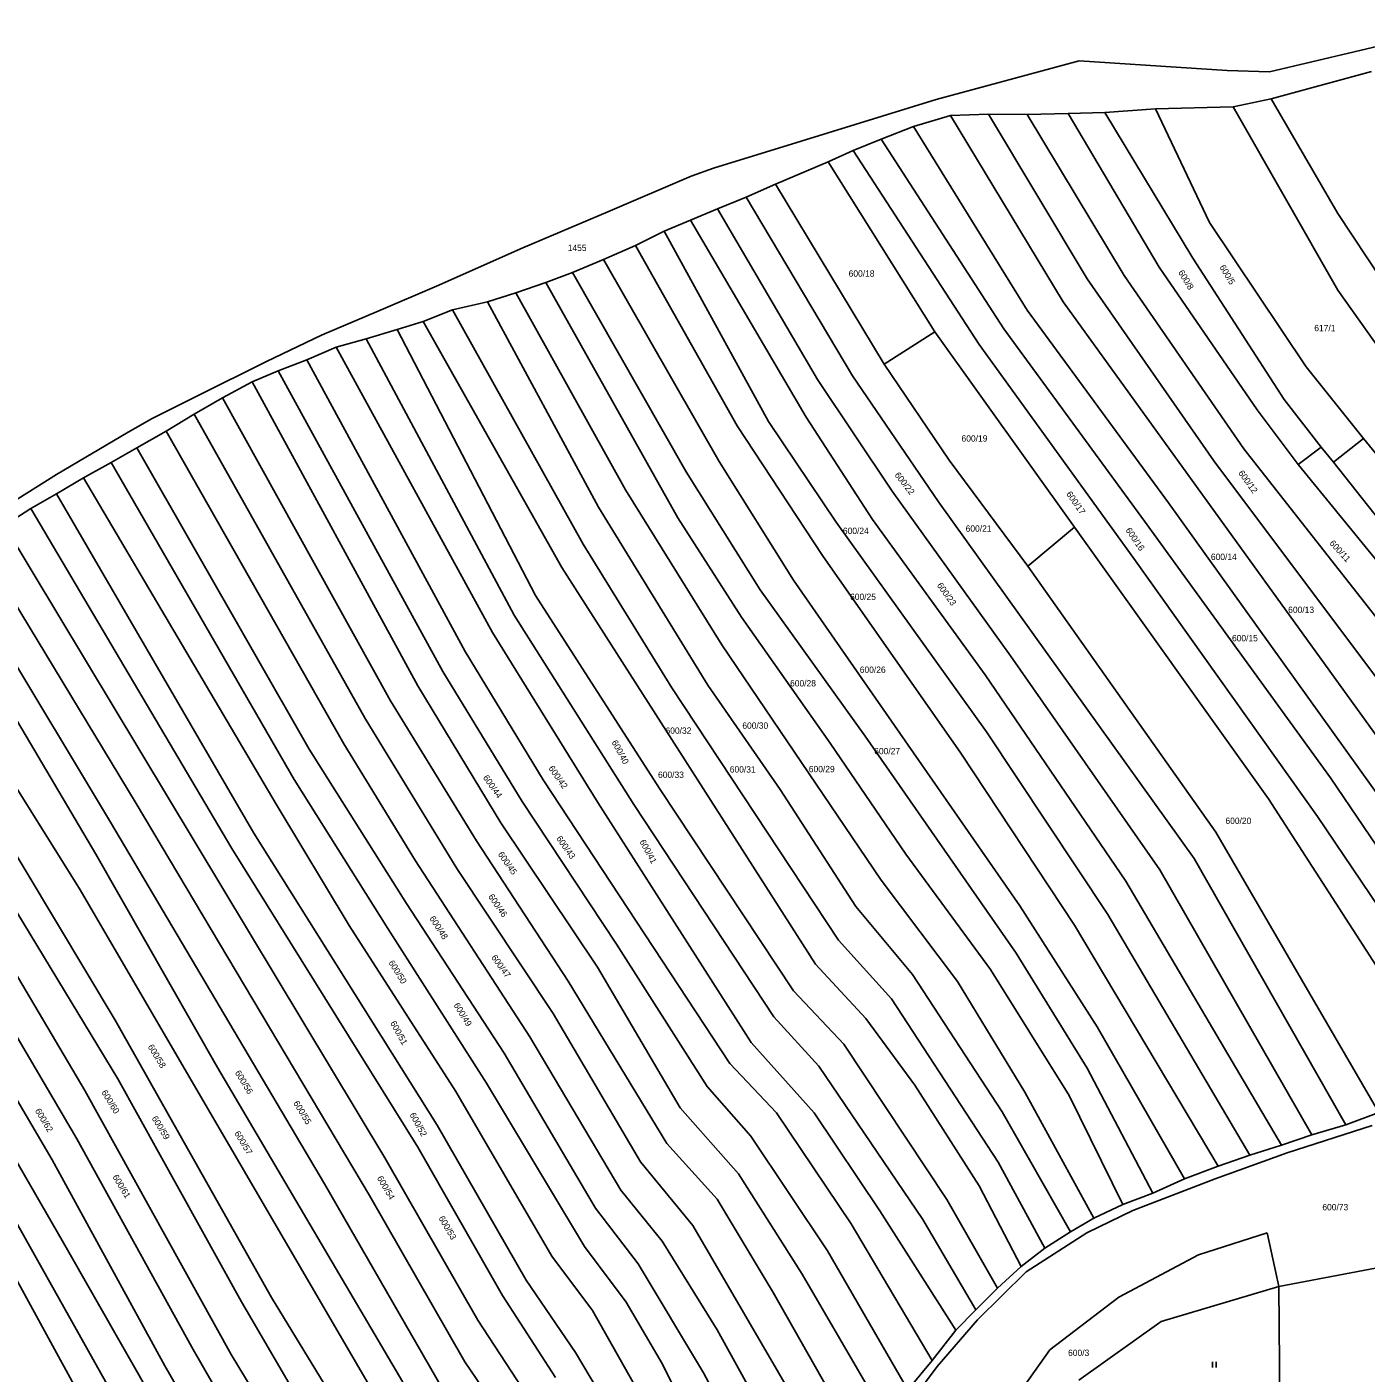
# Model space of a CAD drawing. Extents: x -580630 to -576196, y -1189024 to -1183567.
# Drawn here: x -578490.7 to -578130.8, y -1184779.6 to -1184417.7 of the extents above; entities that cross this region are included whole.
import ezdxf

# ---------------------------------------------------------------- set-up
doc = ezdxf.new("R2010")
doc.units = 0
for name, color, linetype in [('Vrstva 1', 7, 'Continuous'), ('Vrstva 13', 7, 'Continuous'), ('Vrstva 18', 7, 'Continuous'), ('Vrstva 25', 7, 'Continuous'), ('Vrstva 6', 7, 'Continuous')]:
    doc.layers.add(name, color=color, linetype=linetype)

msp = doc.modelspace()

# ---------------------------------------------------------------- linework, layer by layer
at = {"layer": 'Vrstva 1'}
for p, q in [((-578156.31, -1184437.09), (-578129.38, -1184429.69)), ((-578187.46, -1184439.77), (-578201.05, -1184440.75)), ((-578187.46, -1184439.77), (-578166.55, -1184439.17)), ((-578172.89, -1184470.31), (-578187.46, -1184439.77)), ((-578166.55, -1184439.17), (-578156.31, -1184437.09)), ((-578166.55, -1184439.17), (-578138.38, -1184488.49)), ((-578156.31, -1184437.09), (-578138.42, -1184467.91)), ((-578252.43, -1184444.53), (-578242.55, -1184441.49)), ((-578232.31, -1184441.2), (-578242.55, -1184441.49)), ((-578221.93, -1184441.29), (-578232.31, -1184441.2)), ((-578210.85, -1184440.99), (-578221.93, -1184441.29)), ((-578201.05, -1184440.75), (-578210.85, -1184440.99)), ((-578261.15, -1184447.91), (-578252.43, -1184444.53)), ((-578268.68, -1184450.96), (-578275.4, -1184453.97)), ((-578261.15, -1184447.91), (-578268.68, -1184450.96)), ((-578275.4, -1184453.97), (-578289.57, -1184460.03)), ((-578297.45, -1184463.46), (-578289.57, -1184460.03)), ((-578305.17, -1184466.61), (-578297.45, -1184463.46)), ((-578305.17, -1184466.61), (-578312.43, -1184469.69)), ((-578138.42, -1184467.91), (-578094.43, -1184534.57)), ((-578319.47, -1184472.65), (-578327.2, -1184476.49)), ((-578312.43, -1184469.69), (-578319.47, -1184472.65)), ((-578146.91, -1184509.13), (-578172.89, -1184470.31)), ((-578327.2, -1184476.49), (-578335.73, -1184480.22)), ((-578344.12, -1184483.77), (-578335.73, -1184480.22)), ((-578344.12, -1184483.77), (-578351.26, -1184486.44)), ((-578359.37, -1184489.24), (-578351.26, -1184486.44)), ((-578366.97, -1184491.62), (-578359.37, -1184489.24)), ((-578138.38, -1184488.49), (-578086.6, -1184562)), ((-578376.38, -1184493.76), (-578384.2, -1184496.88)), ((-578376.38, -1184493.76), (-578366.97, -1184491.62)), ((-578384.2, -1184496.88), (-578391.26, -1184499.04)), ((-578407.59, -1184503.82), (-578399.53, -1184501.55)), ((-578391.26, -1184499.04), (-578399.53, -1184501.55)), ((-578415.53, -1184507.18), (-578407.59, -1184503.82)), ((-578423.24, -1184510.15), (-578415.53, -1184507.18)), ((-578131.54, -1184528.4), (-578146.91, -1184509.13)), ((-578423.24, -1184510.15), (-578430.23, -1184513.12)), ((-578430.23, -1184513.12), (-578438.2, -1184517.43)), ((-578438.2, -1184517.43), (-578445.8, -1184521.81)), ((-578453.35, -1184526.38), (-578445.8, -1184521.81)), ((-578453.35, -1184526.38), (-578461.15, -1184530.85)), ((-578461.15, -1184530.85), (-578468.08, -1184534.79)), ((-578131.54, -1184528.4), (-578119.43, -1184543.18)), ((-578475.52, -1184538.93), (-578468.08, -1184534.79)), ((-578482.77, -1184543.23), (-578475.52, -1184538.93)), ((-578482.77, -1184543.23), (-578489.64, -1184547.14)), ((-578496.8, -1184551.76), (-578489.64, -1184547.14)), ((-578127.39, -1184709.55), (-578136.23, -1184712.88)), ((-578153.56, -1184718.31), (-578145.43, -1184715.59)), ((-578129.17, -1184713.08), (-578152, -1184720.37)), ((-578136.23, -1184712.88), (-578145.43, -1184715.59)), ((-578162.11, -1184721.07), (-578153.56, -1184718.31)), ((-578152, -1184720.37), (-578171.4, -1184727.37)), ((-578170.61, -1184723.95), (-578162.11, -1184721.07)), ((-578179.6, -1184727.36), (-578170.61, -1184723.95)), ((-578171.4, -1184727.37), (-578193.55, -1184735.94)), ((-578179.6, -1184727.36), (-578188.1, -1184731.21)), ((-578196.23, -1184734.3), (-578188.1, -1184731.21)), ((-578193.55, -1184735.94), (-578205.86, -1184741.95)), ((-578196.23, -1184734.3), (-578203.97, -1184737.94)), ((-578203.97, -1184737.94), (-578210.31, -1184741.62)), ((-578205.86, -1184741.95), (-578222.2, -1184752.38)), ((-578210.31, -1184741.62), (-578217.16, -1184746.05)), ((-578223.52, -1184750.95), (-578217.16, -1184746.05)), ((-578108.43, -1184747.7), (-578154.28, -1184756.3)), ((-578229.92, -1184756.76), (-578223.52, -1184750.95)), ((-578222.2, -1184752.38), (-578235.29, -1184765.29)), ((-578235.69, -1184762.57), (-578229.92, -1184756.76)), ((-578154.28, -1184756.3), (-578185.88, -1184765.76)), ((-578235.69, -1184762.57), (-578241.12, -1184768.09)), ((-578235.29, -1184765.29), (-578246.12, -1184777.8)), ((-578185.88, -1184765.76), (-578208.03, -1184781.52)), ((-578241.12, -1184768.09), (-578247.45, -1184776.2)), ((-578247.45, -1184776.2), (-578253.94, -1184784.14)), ((-578246.12, -1184777.8), (-578270.55, -1184810.61))]:
    msp.add_line(p, q, dxfattribs=at)
at = {"layer": 'Vrstva 13'}
for p, q in [((-578156.78, -1184429.77), (-578105.77, -1184417.72)), ((-578207.91, -1184426.86), (-578246.37, -1184437.25)), ((-578168.12, -1184429.45), (-578207.91, -1184426.86)), ((-578156.78, -1184429.77), (-578168.12, -1184429.45)), ((-578246.37, -1184437.25), (-578282.66, -1184448.44)), ((-578282.66, -1184448.44), (-578306.17, -1184455.7)), ((-578312.25, -1184457.84), (-578334.61, -1184467.4)), ((-578306.17, -1184455.7), (-578312.25, -1184457.84)), ((-578334.61, -1184467.4), (-578357.46, -1184477.13)), ((-578357.46, -1184477.13), (-578380.66, -1184487.42)), ((-578380.66, -1184487.42), (-578396.11, -1184494.01)), ((-578396.11, -1184494.01), (-578411.56, -1184500.61)), ((-578411.56, -1184500.61), (-578426.36, -1184507.69)), ((-578426.36, -1184507.69), (-578444.93, -1184516.92)), ((-578444.93, -1184516.92), (-578457.09, -1184523.02)), ((-578457.09, -1184523.02), (-578463.5, -1184526.64)), ((-578463.5, -1184526.64), (-578482.74, -1184538.01)), ((-578482.74, -1184538.01), (-578495.55, -1184546.08))]:
    msp.add_line(p, q, dxfattribs=at)
at = {"layer": 'Vrstva 25'}
for p, q in [((-578172.08, -1184776.59), (-578172.08, -1184778.09)), ((-578171.08, -1184778.09), (-578171.08, -1184776.59))]:
    msp.add_line(p, q, dxfattribs=at)
at = {"layer": 'Vrstva 6'}
for p, q in [((-578242.55, -1184441.49), (-578212.23, -1184491.59)), ((-578232.31, -1184441.2), (-578205.82, -1184485.43)), ((-578221.93, -1184441.29), (-578195.84, -1184484.58)), ((-578210.85, -1184440.99), (-578186.47, -1184482.33)), ((-578201.05, -1184440.75), (-578177.42, -1184479.87)), ((-578221.92, -1184493.83), (-578252.43, -1184444.53)), ((-578268.68, -1184450.96), (-578234.81, -1184503.08)), ((-578228.22, -1184498.85), (-578261.15, -1184447.91)), ((-578275.4, -1184453.97), (-578246.75, -1184499.69)), ((-578289.57, -1184460.03), (-578260.33, -1184508.4)), ((-578268.89, -1184511.56), (-578297.45, -1184463.46)), ((-578278.3, -1184512.52), (-578305.17, -1184466.61)), ((-578319.47, -1184472.65), (-578291.4, -1184523.78)), ((-578312.43, -1184469.69), (-578281.33, -1184522.6)), ((-578327.2, -1184476.49), (-578299.89, -1184524.96)), ((-578335.73, -1184480.22), (-578304.72, -1184534.51)), ((-578177.42, -1184479.87), (-578152.81, -1184517.84)), ((-578313.6, -1184537.37), (-578344.12, -1184483.77)), ((-578186.47, -1184482.33), (-578160.09, -1184520.7)), ((-578351.26, -1184486.44), (-578315.84, -1184549.72)), ((-578205.82, -1184485.43), (-578171.76, -1184534.39)), ((-578195.84, -1184484.58), (-578163.65, -1184531.11)), ((-578329.83, -1184542.14), (-578359.37, -1184489.24)), ((-578341.23, -1184556.75), (-578376.38, -1184493.76)), ((-578337.08, -1184546.81), (-578366.97, -1184491.62)), ((-578183.92, -1184545.64), (-578221.92, -1184493.83)), ((-578212.23, -1184491.59), (-578106.99, -1184637.51)), ((-578384.2, -1184496.88), (-578346.97, -1184563.07)), ((-578399.53, -1184501.55), (-578359.78, -1184575.85)), ((-578391.26, -1184499.04), (-578354.01, -1184570.53)), ((-578260.33, -1184508.4), (-578246.75, -1184499.69)), ((-578246.75, -1184499.69), (-578209.22, -1184552.23)), ((-578228.22, -1184498.85), (-578190.35, -1184550.58)), ((-578365.59, -1184580.52), (-578407.59, -1184503.82)), ((-578234.81, -1184503.08), (-578193.28, -1184560.62)), ((-578372.93, -1184585.59), (-578415.53, -1184507.18)), ((-578260.33, -1184508.4), (-578242.91, -1184534.22)), ((-578378.95, -1184590.97), (-578423.24, -1184510.15)), ((-578258.21, -1184542.51), (-578278.3, -1184512.52)), ((-578245.76, -1184545.35), (-578268.89, -1184511.56)), ((-578430.23, -1184513.12), (-578385.69, -1184594.83)), ((-578438.2, -1184517.43), (-578393.03, -1184598.9)), ((-578152.81, -1184517.84), (-578142.92, -1184530.67)), ((-578445.8, -1184521.81), (-578399.86, -1184603.6)), ((-578291.4, -1184523.78), (-578273.2, -1184550.88)), ((-578281.33, -1184522.6), (-578263.49, -1184550.1)), ((-578160.09, -1184520.7), (-578149.11, -1184535.32)), ((-578405.54, -1184610.41), (-578453.35, -1184526.38)), ((-578299.89, -1184524.96), (-578276.95, -1184559.84)), ((-578461.15, -1184530.85), (-578414.86, -1184611.87)), ((-578163.65, -1184531.11), (-578110.58, -1184598.87)), ((-578149.11, -1184535.32), (-578142.92, -1184530.67)), ((-578142.92, -1184530.67), (-578139.61, -1184534.75)), ((-578139.61, -1184534.75), (-578131.54, -1184528.4)), ((-578304.72, -1184534.51), (-578284.74, -1184566.43)), ((-578242.91, -1184534.22), (-578221.75, -1184562.69)), ((-578171.76, -1184534.39), (-578113.17, -1184612.6)), ((-578468.08, -1184534.79), (-578418.91, -1184620)), ((-578293.69, -1184569.09), (-578313.6, -1184537.37)), ((-578107.23, -1184586.66), (-578149.11, -1184535.32)), ((-578096, -1184589.87), (-578139.61, -1184534.75)), ((-578423.72, -1184626.7), (-578475.52, -1184538.93)), ((-578429.74, -1184634.44), (-578482.77, -1184543.23)), ((-578303.93, -1184583.83), (-578329.83, -1184542.14)), ((-578226.41, -1184586.75), (-578258.21, -1184542.51)), ((-578177.04, -1184641.3), (-578245.76, -1184545.35)), ((-578489.64, -1184547.14), (-578435.69, -1184638.6)), ((-578307.75, -1184594.66), (-578337.08, -1184546.81)), ((-578115.05, -1184641.8), (-578183.92, -1184545.64)), ((-578394.57, -1184721.78), (-578496.8, -1184551.76)), ((-578315.84, -1184549.72), (-578298.7, -1184576.42)), ((-578273.2, -1184550.88), (-578232.82, -1184607.23)), ((-578263.49, -1184550.1), (-578233.17, -1184591.87)), ((-578221.75, -1184562.69), (-578209.22, -1184552.23)), ((-578209.22, -1184552.23), (-578157.06, -1184625.25)), ((-578140.39, -1184619.63), (-578190.35, -1184550.58)), ((-578503.77, -1184556.47), (-578461.4, -1184626.51)), ((-578317.41, -1184595.35), (-578341.23, -1184556.75)), ((-578276.95, -1184559.84), (-578239.73, -1184612.95)), ((-578510.81, -1184560.71), (-578468.27, -1184631.48)), ((-578346.97, -1184563.07), (-578278.82, -1184669.68)), ((-578221.75, -1184562.69), (-578171.23, -1184634.24)), ((-578193.28, -1184560.62), (-578143.85, -1184629.97)), ((-578472.18, -1184640.07), (-578517.19, -1184564.06)), ((-578284.74, -1184566.43), (-578223.88, -1184654.02)), ((-578526.16, -1184570.28), (-578476.72, -1184649.27)), ((-578354.01, -1184570.53), (-578320.74, -1184622.44)), ((-578265.45, -1184608.41), (-578293.69, -1184569.09)), ((-578467.05, -1184684.78), (-578532.58, -1184575.28)), ((-578359.78, -1184575.85), (-578327.64, -1184626.72)), ((-578298.7, -1184576.42), (-578274.88, -1184610.31)), ((-578466.3, -1184700.51), (-578539.08, -1184580.57)), ((-578337.29, -1184626.21), (-578365.59, -1184580.52)), ((-578261.19, -1184647.07), (-578303.93, -1184583.83)), ((-578351.96, -1184620.16), (-578372.93, -1184585.59)), ((-578186.24, -1184644.33), (-578226.41, -1184586.75)), ((-578357.64, -1184625.94), (-578378.95, -1184590.97)), ((-578233.17, -1184591.87), (-578195.37, -1184647.34)), ((-578475.15, -1184703.67), (-578540.44, -1184593.37)), ((-578385.69, -1184594.83), (-578363.33, -1184631.68)), ((-578272.6, -1184663.23), (-578317.41, -1184595.35)), ((-578288.25, -1184622.75), (-578307.75, -1184594.66)), ((-578393.03, -1184598.9), (-578369.9, -1184636.5)), ((-578399.86, -1184603.6), (-578375.22, -1184643.95)), ((-578386.32, -1184641.89), (-578405.54, -1184610.41)), ((-578274.88, -1184610.31), (-578254.5, -1184640.07)), ((-578224.88, -1184666.74), (-578265.45, -1184608.41)), ((-578232.82, -1184607.23), (-578200.23, -1184656.31)), ((-578414.86, -1184611.87), (-578388.76, -1184653.4)), ((-578239.73, -1184612.95), (-578209.21, -1184659.17)), ((-578477.35, -1184716.6), (-578534.83, -1184618.74)), ((-578418.91, -1184620), (-578393.77, -1184660.05)), ((-578301.82, -1184696.43), (-578351.96, -1184620.16)), ((-578121.42, -1184647.66), (-578140.39, -1184619.63)), ((-578541.8, -1184623.66), (-578483.99, -1184722.3)), ((-578320.74, -1184622.44), (-578284.72, -1184676.89)), ((-578268, -1184654.22), (-578288.25, -1184622.75)), ((-578548.65, -1184627.18), (-578480.91, -1184744.64)), ((-578461.4, -1184626.51), (-578398.69, -1184731.85)), ((-578404.16, -1184659.27), (-578423.72, -1184626.7)), ((-578332.31, -1184664.27), (-578357.64, -1184625.94)), ((-578296.06, -1184690.75), (-578337.29, -1184626.21)), ((-578327.64, -1184626.72), (-578290, -1184683.8)), ((-578157.06, -1184625.25), (-578109.61, -1184698.84)), ((-578468.27, -1184631.48), (-578410.79, -1184728.73)), ((-578363.33, -1184631.68), (-578337.38, -1184670.52)), ((-578143.85, -1184629.97), (-578102.4, -1184691.57)), ((-578380.48, -1184712.95), (-578429.74, -1184634.44)), ((-578171.23, -1184634.24), (-578127.39, -1184709.55)), ((-578435.69, -1184638.6), (-578385.64, -1184718.85)), ((-578369.9, -1184636.5), (-578345.24, -1184674.29)), ((-578439.51, -1184697.42), (-578472.18, -1184640.07)), ((-578355.57, -1184689.26), (-578386.32, -1184641.89)), ((-578254.5, -1184640.07), (-578231.77, -1184671.1)), ((-578136.23, -1184712.88), (-578177.04, -1184641.3)), ((-578375.22, -1184643.95), (-578349.28, -1184682.94)), ((-578145.43, -1184715.59), (-578186.24, -1184644.33)), ((-578476.72, -1184649.27), (-578390.21, -1184797.54)), ((-578240.61, -1184674.36), (-578261.19, -1184647.07)), ((-578195.37, -1184647.34), (-578153.56, -1184718.31)), ((-578388.76, -1184653.4), (-578362.46, -1184693.61)), ((-578223.88, -1184654.02), (-578203.11, -1184686.53)), ((-578252.72, -1184672.49), (-578268, -1184654.22)), ((-578200.23, -1184656.31), (-578162.11, -1184721.07)), ((-578375.42, -1184703.94), (-578404.16, -1184659.27)), ((-578393.77, -1184660.05), (-578367.2, -1184701.65)), ((-578209.21, -1184659.17), (-578170.61, -1184723.95)), ((-578307.92, -1184702.59), (-578332.31, -1184664.27)), ((-578258.33, -1184678.97), (-578272.6, -1184663.23)), ((-578205.78, -1184697.68), (-578224.88, -1184666.74)), ((-578337.38, -1184670.52), (-578315.18, -1184708.29)), ((-578278.82, -1184669.68), (-578265.26, -1184684.31)), ((-578231.77, -1184671.1), (-578210.6, -1184704.99)), ((-578345.24, -1184674.29), (-578318.78, -1184717.86)), ((-578228.62, -1184709.41), (-578252.72, -1184672.49)), ((-578222.5, -1184704.13), (-578240.61, -1184674.36)), ((-578284.72, -1184676.89), (-578271.17, -1184691.18)), ((-578229.72, -1184722.94), (-578258.33, -1184678.97)), ((-578349.28, -1184682.94), (-578325.85, -1184722.83)), ((-578425.03, -1184759.32), (-578467.05, -1184684.78)), ((-578290, -1184683.8), (-578277.94, -1184697.09)), ((-578265.26, -1184684.31), (-578252.11, -1184702.22)), ((-578203.11, -1184686.53), (-578179.6, -1184727.36)), ((-578331.11, -1184730.42), (-578355.57, -1184689.26)), ((-578362.46, -1184693.61), (-578337.91, -1184735.31)), ((-578279.2, -1184709.63), (-578296.06, -1184690.75)), ((-578271.17, -1184691.18), (-578243.51, -1184732.92)), ((-578386.74, -1184787.03), (-578439.51, -1184697.42)), ((-578289.24, -1184709.63), (-578301.82, -1184696.43)), ((-578277.94, -1184697.09), (-578249.99, -1184738.34)), ((-578433.09, -1184760.45), (-578466.3, -1184700.51)), ((-578188.1, -1184731.21), (-578205.78, -1184697.68)), ((-578435.82, -1184774.58), (-578475.15, -1184703.67)), ((-578349.65, -1184748.2), (-578375.42, -1184703.94)), ((-578367.2, -1184701.65), (-578340.92, -1184745.58)), ((-578296.22, -1184715.88), (-578307.92, -1184702.59)), ((-578252.11, -1184702.22), (-578234.79, -1184729.28)), ((-578203.97, -1184737.94), (-578222.5, -1184704.13)), ((-578315.18, -1184708.29), (-578299.47, -1184726.07)), ((-578210.6, -1184704.99), (-578196.23, -1184734.3)), ((-578269.24, -1184739.51), (-578289.24, -1184709.63)), ((-578261.47, -1184735.96), (-578279.2, -1184709.63)), ((-578210.31, -1184741.62), (-578228.62, -1184709.41)), ((-578356.54, -1184754.65), (-578380.48, -1184712.95)), ((-578446.42, -1184772.65), (-578477.35, -1184716.6)), ((-578385.64, -1184718.85), (-578362.93, -1184758.71)), ((-578318.78, -1184717.86), (-578305.24, -1184732.9)), ((-578275.6, -1184746.75), (-578296.22, -1184715.88)), ((-578483.99, -1184722.3), (-578453.67, -1184777.7)), ((-578369.53, -1184765.37), (-578394.57, -1184721.78)), ((-578325.85, -1184722.83), (-578311.79, -1184739.96)), ((-578299.47, -1184726.07), (-578282.34, -1184752.99)), ((-578217.16, -1184746.05), (-578229.72, -1184722.94)), ((-578410.79, -1184728.73), (-578379.16, -1184783.63)), ((-578234.79, -1184729.28), (-578223.52, -1184750.95)), ((-578449.19, -1184818.22), (-578497.84, -1184731.52)), ((-578398.69, -1184731.85), (-578373.08, -1184776.56)), ((-578320.02, -1184744.15), (-578331.11, -1184730.42)), ((-578305.24, -1184732.9), (-578290.22, -1184757.99)), ((-578243.51, -1184732.92), (-578229.92, -1184756.76)), ((-578337.91, -1184735.31), (-578326.47, -1184750.26)), ((-578241.12, -1184768.09), (-578261.47, -1184735.96)), ((-578311.79, -1184739.96), (-578271.79, -1184808.45)), ((-578247.45, -1184776.2), (-578269.24, -1184739.51)), ((-578249.99, -1184738.34), (-578235.69, -1184762.57)), ((-578457.94, -1184819.46), (-578499.9, -1184742.89)), ((-578305.25, -1184768.02), (-578320.02, -1184744.15)), ((-578157.43, -1184741.94), (-578175.84, -1184747.85)), ((-578154.82, -1184753.83), (-578157.43, -1184741.94)), ((-578480.91, -1184744.64), (-578437.74, -1184820.12)), ((-578338.72, -1184762.79), (-578349.65, -1184748.2)), ((-578340.92, -1184745.58), (-578329.72, -1184760.52)), ((-578253.94, -1184784.14), (-578275.6, -1184746.75)), ((-578175.84, -1184747.85), (-578197.3, -1184759.18)), ((-578326.47, -1184750.26), (-578308.91, -1184779.54)), ((-578343.26, -1184774.06), (-578356.54, -1184754.65)), ((-578282.34, -1184752.99), (-578259.89, -1184791.65)), ((-578154.28, -1184756.3), (-578154.82, -1184753.83)), ((-578362.93, -1184758.71), (-578348.68, -1184780.83)), ((-578290.22, -1184757.99), (-578266.19, -1184800.21)), ((-578154.28, -1184756.3), (-578153.89, -1184794.78)), ((-578406.88, -1184805.16), (-578433.09, -1184760.45)), ((-578398.63, -1184802.34), (-578425.03, -1184759.32)), ((-578329.72, -1184760.52), (-578319.94, -1184777.21)), ((-578197.3, -1184759.18), (-578215.81, -1184773.37)), ((-578355.98, -1184786.13), (-578369.53, -1184765.37)), ((-578324.67, -1184787.71), (-578338.72, -1184762.79)), ((-578280.97, -1184811.67), (-578305.25, -1184768.02)), ((-578421.6, -1184815.71), (-578446.42, -1184772.65)), ((-578215.81, -1184773.37), (-578230.58, -1184794.06)), ((-578416.58, -1184806.44), (-578435.82, -1184774.58)), ((-578373.08, -1184776.56), (-578362.16, -1184792.55)), ((-578332.17, -1184792.85), (-578343.26, -1184774.06)), ((-578453.67, -1184777.7), (-578431.91, -1184814.94)), ((-578319.94, -1184777.21), (-578299.77, -1184817.74)), ((-578308.91, -1184779.54), (-578290.14, -1184814.68))]:
    msp.add_line(p, q, dxfattribs=at)

# ---------------------------------------------------------------- texts
at = {"layer": 'Vrstva 18'}
for s, p in [('1455', (-578345.389, -1184477.97)), ('600/18', (-578269.888, -1184484.86)), ('617/1', (-578144.747, -1184499.52)), ('600/19', (-578239.548, -1184529.19)), ('600/24', (-578271.43, -1184554.03)), ('600/21', (-578238.442, -1184553.42)), ('600/14', (-578172.528, -1184561.02)), ('600/25', (-578269.506, -1184571.77)), ('600/13', (-578151.755, -1184575.25)), ('600/15', (-578166.865, -1184582.89)), ('600/26', (-578266.9, -1184591.37)), ('600/28', (-578285.63, -1184595.02)), ('600/32', (-578319.107, -1184607.75)), ('600/30', (-578298.46, -1184606.4)), ('600/27', (-578263.019, -1184613.25)), ('600/33', (-578321.12, -1184619.61)), ('600/31', (-578301.835, -1184618.17)), ('600/29', (-578280.59, -1184618.08)), ('600/20', (-578168.616, -1184631.98)), ('600/73', (-578142.583, -1184735.85)), ('600/3', (-578210.914, -1184775.02))]:
    msp.add_text(s, height=1.7, dxfattribs=at).set_placement(p)
for s, rotation, p in [('600/8', 301.08932, (-578181.401, -1184483.707)), ('600/5', 300.74555, (-578170.276, -1184482.303)), ('600/22', 307.96481, (-578257.62, -1184538.212)), ('600/12', 305.95946, (-578165.281, -1184537.672)), ('600/17', 305.04273, (-578211.515, -1184543.289)), ('600/16', 304.64166, (-578195.556, -1184553.041)), ('600/11', 312.54848, (-578140.783, -1184556.636)), ('600/23', 305.73028, (-578246.262, -1184567.86)), ('600/40', 298.39642, (-578333.659, -1184610.003)), ('600/42', 305.04273, (-578350.65, -1184617.041)), ('600/44', 305.04273, (-578368.248, -1184619.551)), ('600/43', 305.04273, (-578348.558, -1184635.91)), ('600/45', 305.04273, (-578364.255, -1184640.143)), ('600/41', 298.39642, (-578326.15, -1184636.733)), ('600/46', 305.04273, (-578366.848, -1184651.541)), ('600/48', 302.46442, (-578382.622, -1184657.37)), ('600/47', 305.90217, (-578366.025, -1184667.92)), ('600/50', 301.66228, (-578393.621, -1184669.263)), ('600/49', 301.66228, (-578376.112, -1184680.696)), ('600/51', 298.6256, (-578393.156, -1184685.499)), ('600/58', 301.26121, (-578458.322, -1184691.873)), ('600/56', 301.26121, (-578434.911, -1184698.86)), ('600/60', 301.26121, (-578470.791, -1184704.148)), ('600/55', 301.26121, (-578419.206, -1184707.04)), ('600/62', 301.26121, (-578488.645, -1184709.097)), ('600/59', 301.26121, (-578457.261, -1184711.12)), ('600/52', 298.6256, (-578387.938, -1184710.129)), ('600/57', 301.26121, (-578435.071, -1184715.165)), ('600/61', 301.26121, (-578467.806, -1184726.858)), ('600/54', 300.40177, (-578396.717, -1184727.198)), ('600/53', 300.40177, (-578380.161, -1184737.963))]:
    msp.add_text(s, height=1.7, rotation=rotation, dxfattribs=at).set_placement(p)

doc.saveas('drawing.dxf')
